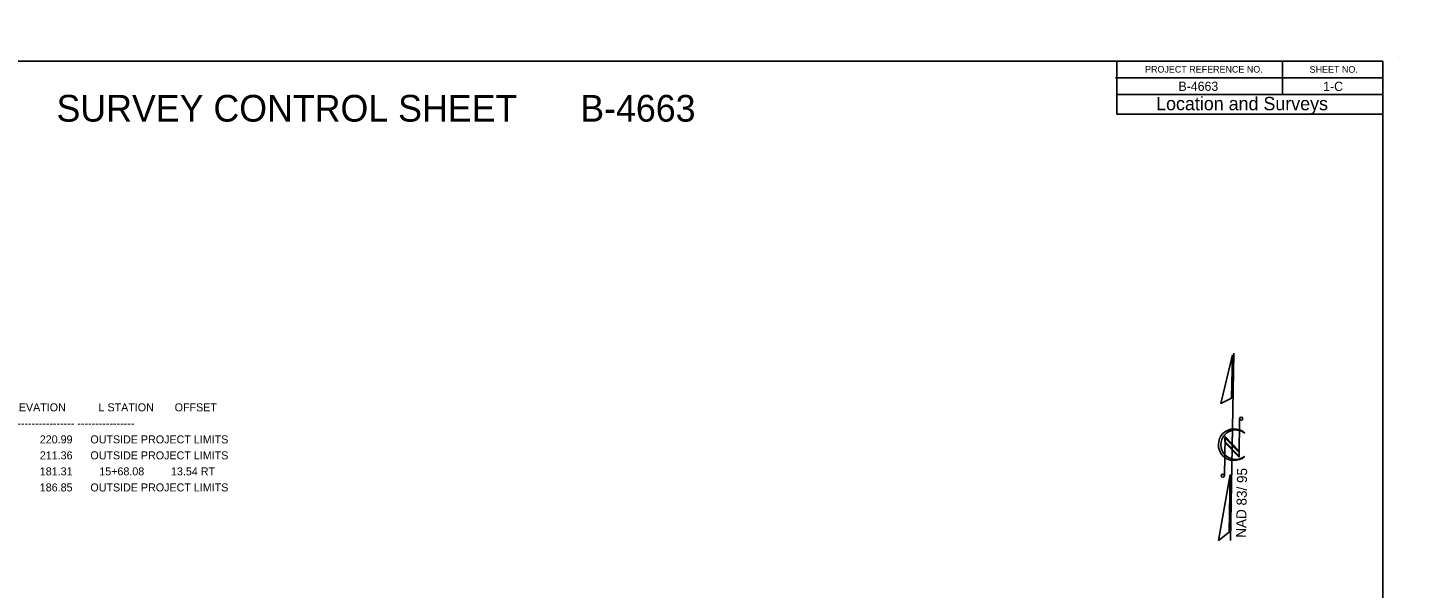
# Model space of a CAD drawing. Extents: x 2169223 to 2172151, y 723262 to 725175.
# Drawn here: x 2170358 to 2172151, y 724446 to 725175 of the extents above; entities that cross this region are included whole.
import ezdxf

# ---------------------------------------------------------------- set-up
doc = ezdxf.new("R2010")
doc.units = 0
for name, color, linetype in [('CTL Sheet Border CELL', 7, 'Continuous'), ('CTL Sheet Text', 7, 'Continuous'), ('Sheet North Arrow CELL', 7, 'Continuous')]:
    doc.layers.add(name, color=color, linetype=linetype)

msp = doc.modelspace()

# ---------------------------------------------------------------- linework, layer by layer
at = {"layer": 'CTL Sheet Border CELL'}
for p, q in [((2172151.5, 725175.4), (2172151.5, 725175.4)), ((2171775.9, 725131.8), (2171775.9, 725088.4)), ((2171991.5, 725131.8), (2171991.5, 725088.4)), ((2172143.6, 725136.4), (2172143.6, 725136.4)), ((2172143.6, 725136.4), (2172143.6, 725136.4)), ((2171774, 725110.1), (2172121.9, 725110.1))]:
    msp.add_line(p, q, dxfattribs=at)
for points in [[(2172121.9, 725131.9), (2169513.2, 725131.8), (2169513.2, 723305.8), (2172121.9, 723305.8)], [(2171775.9, 725088.4), (2172121.9, 725088.4), (2172121.9, 725062.8), (2171775.9, 725062.8)]]:
    msp.add_lwpolyline(points, close=True, dxfattribs=at)
at = {"layer": 'Sheet North Arrow CELL'}
for p, q in [((2171923.8, 724507.9), (2171928, 724751.6)), ((2171935.7, 724666.6), (2171934.9, 724616.6)), ((2171916.7, 724643.3), (2171915.8, 724592.5)), ((2171935, 724622.6), (2171916.6, 724641.5)), ((2171916.6, 724641.5), (2171916.6, 724636.9)), ((2171935, 724624.4), (2171916.7, 724643.3)), ((2171942.3, 724647.9), (2171942.6, 724647.7)), ((2171934.9, 724616.6), (2171916.5, 724635.5)), ((2171934.9, 724618), (2171916.6, 724636.9)), ((2171916.6, 724636.9), (2171934.9, 724618)), ((2171934.9, 724618), (2171935, 724622.6))]:
    msp.add_line(p, q, dxfattribs=at)
for points in [[(2171926.2, 724749.5), (2171911.2, 724686.4), (2171925.3, 724693.2)], [(2171923.3, 724593.8), (2171908.1, 724508.1), (2171922, 724518.8)]]:
    msp.add_lwpolyline(points, close=True, dxfattribs=at)
for centre in [(2171937.7, 724666.5), (2171913.8, 724592.5)]:
    msp.add_circle(centre, 1.99, dxfattribs=at)
for centre, radius, start, end in [((2171928.5, 724632.7), 20.5, 46.8737, 311.4277), ((2171930.5, 724632.7), 19.2, 52.1287, 307.6624)]:
    msp.add_arc(centre, radius, start, end, dxfattribs=at)

# ---------------------------------------------------------------- texts
at = {"layer": 'CTL Sheet Border CELL'}
for s, height, p in [('PROJECT REFERENCE NO.', 8.696, (2171812.6, 725116.8)), ('SHEET NO.', 8.7, (2172026.8, 725116.6)), ('B-4663', 12, (2171856.1, 725093)), ('1-C', 12, (2172044.4, 725092.9)), ('SURVEY CONTROL SHEET ', 34.783, (2170396, 725053)), ('B-4663', 34.78, (2171077.6, 725053)), ('Location and Surveys', 17.392, (2171827, 725067.8))]:
    msp.add_text(s, height=height, rotation=0.0018, dxfattribs=at).set_placement(p)
at = {"layer": 'CTL Sheet Text'}
for s, p in [('    POINT          DESC.           NORTH             EAST          ELEVATION           L STATION       OFFSET', (2169973.1, 724676.1)), ('------------ ---------------- ---------------- ---------------- ---------------- ---------------- ----------------', (2169973.1, 724655.3)), ('100                    BL-100      724092.6980     2169932.1360           220.99      OUTSIDE PROJECT LIMITS                 ', (2169973.1, 724634.4)), ('101                    BL-101      724081.2660     2170337.6640           211.36      OUTSIDE PROJECT LIMITS                 ', (2169973.1, 724613.6)), ('102                    BL-102      724058.9930     2170968.2540           181.31         15+68.08         13.54 RT', (2169973.1, 724592.8)), ('103                    BL-103      724027.2880     2171653.5320           186.85      OUTSIDE PROJECT LIMITS                 ', (2169973.1, 724571.9))]:
    msp.add_text(s, height=10.4167, dxfattribs=at).set_placement(p)
at = {"layer": 'Sheet North Arrow CELL'}
msp.add_text('NAD 83/ 95', height=13.12, rotation=89.0337, dxfattribs=at).set_placement((2171944, 724511.6))

doc.saveas('drawing.dxf')
